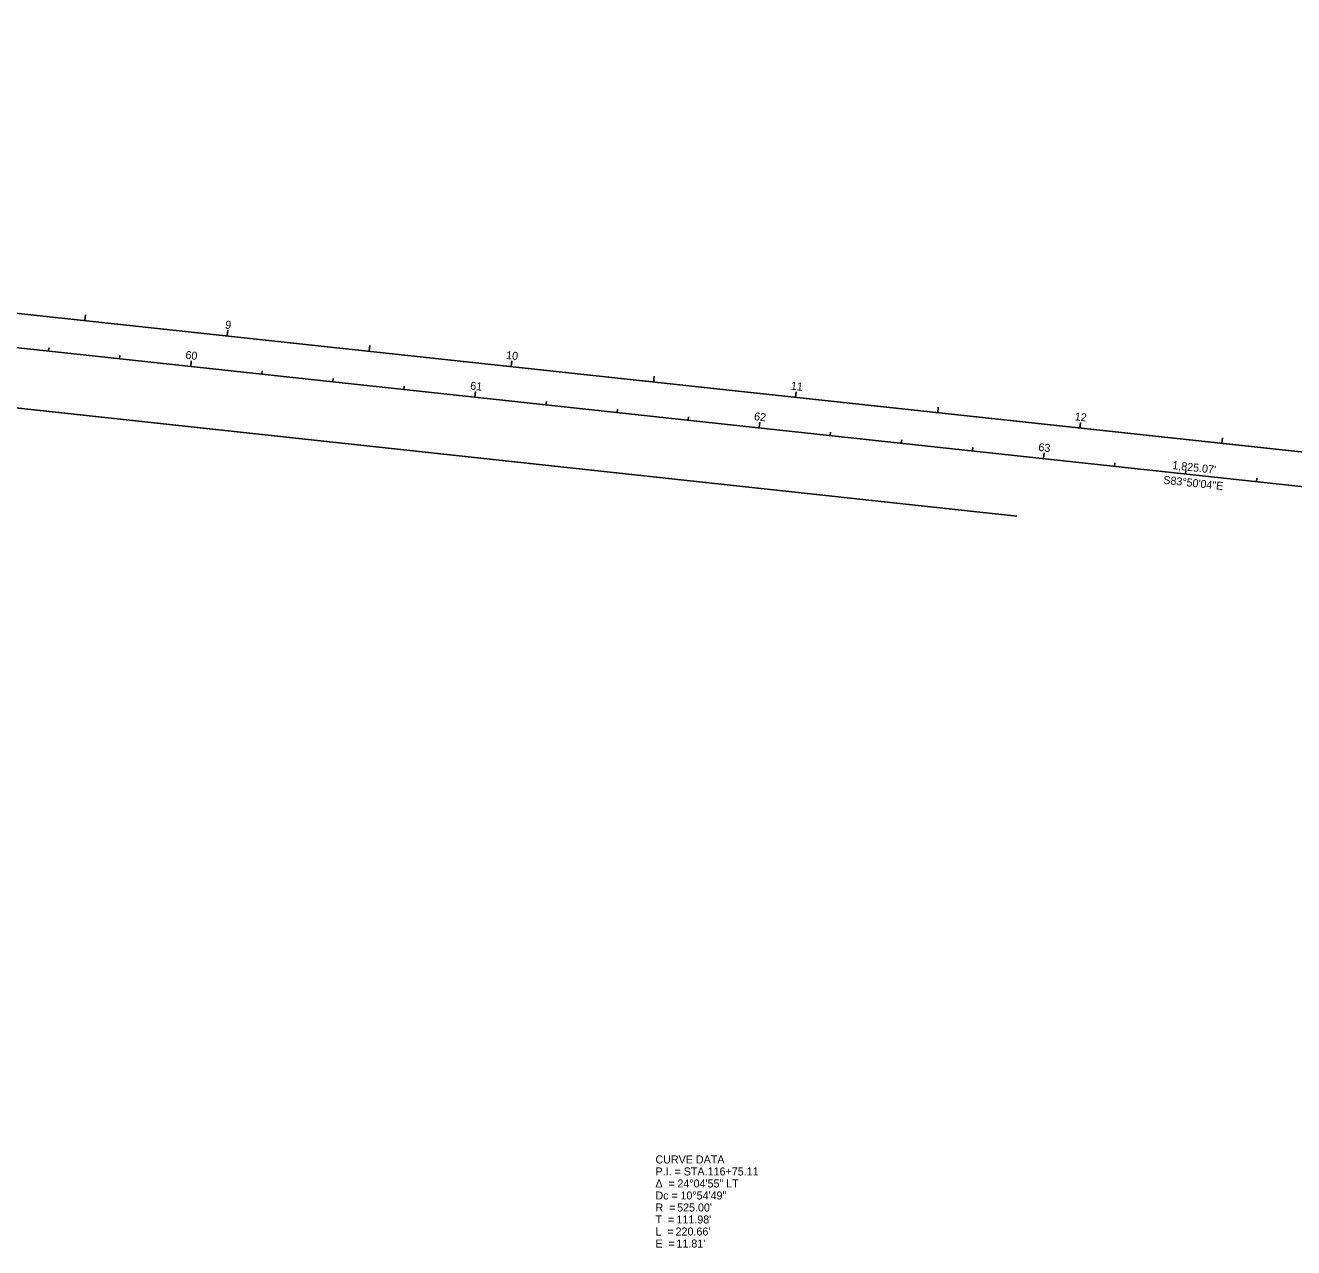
# Model space of a CAD drawing. Extents: x 1363416 to 1365241, y 422393 to 423801.
# Drawn here: x 1364353.9 to 1364797.5, y 422787.9 to 423215.5 of the extents above; entities that cross this region are included whole.
import ezdxf

# ---------------------------------------------------------------- set-up
doc = ezdxf.new("R2010")
doc.units = 0
for name, color, linetype in [('_CIVIL_CONSTRUCTION', 7, 'Continuous'), ('DT_X_Break_Line', 7, 'Continuous'), ('DT_X_Contour_Major', 7, 'Continuous'), ('DT_X_Contour_Minor', 7, 'Continuous'), ('DT_X_Spot_Elev', 7, 'Continuous'), ('MD_P_SAWCUT', 7, 'Continuous'), ('PF_X_Ground_Line', 7, 'Continuous')]:
    doc.layers.add(name, color=color, linetype=linetype)

msp = doc.modelspace()

# ---------------------------------------------------------------- linework, layer by layer
at = {"layer": '_CIVIL_CONSTRUCTION'}
msp.add_line((1363417.51, 423203.55), (1365232.02, 423007.54), dxfattribs=at)
at = {"layer": 'DT_X_Break_Line'}
for p, q in [((1363418.8, 423215.48), (1365233.31, 423019.47)), ((1363773.17, 423144.01), (1364700.72, 423043.81)), ((1363773.17, 423144.01), (1364700.72, 423043.81)), ((1363773.17, 423144.01), (1364700.72, 423043.81)), ((1364295.51, 423120.77), (1365233.31, 423019.47)), ((1365233.31, 423019.47), (1364295.51, 423120.77)), ((1364374.74, 423112.21), (1364374.96, 423114.2)), ((1364424.46, 423106.84), (1364424.67, 423108.83)), ((1364474.17, 423101.47), (1364474.38, 423103.46)), ((1364523.88, 423096.1), (1364524.09, 423098.09)), ((1364573.59, 423090.73), (1364573.8, 423092.72)), ((1364291.61, 423088), (1364700.72, 423043.81)), ((1364291.61, 423088), (1364700.72, 423043.81)), ((1364623.3, 423085.36), (1364623.51, 423087.35)), ((1364673.01, 423079.99), (1364673.22, 423081.98)), ((1364722.72, 423074.62), (1364722.94, 423076.61)), ((1364772.43, 423069.25), (1364772.65, 423071.24))]:
    msp.add_line(p, q, dxfattribs=at)
at = {"layer": 'DT_X_Contour_Major'}
for p, q in [((1364362.01, 423101.52), (1364362.14, 423102.71)), ((1364386.87, 423098.83), (1364387, 423100.03)), ((1364411.72, 423096.15), (1364411.94, 423098.14)), ((1364436.58, 423093.46), (1364436.71, 423094.66)), ((1364461.44, 423090.78), (1364461.56, 423091.97)), ((1364486.29, 423088.09), (1364486.42, 423089.29)), ((1364511.15, 423085.41), (1364511.36, 423087.4)), ((1364536, 423082.72), (1364536.13, 423083.92)), ((1364560.86, 423080.04), (1364560.99, 423081.23)), ((1364585.71, 423077.35), (1364585.84, 423078.55)), ((1364610.57, 423074.67), (1364610.78, 423076.66)), ((1364635.42, 423071.98), (1364635.55, 423073.18)), ((1364660.28, 423069.3), (1364660.41, 423070.49)), ((1364685.13, 423066.61), (1364685.26, 423067.81)), ((1364709.99, 423063.93), (1364710.2, 423065.92)), ((1364734.84, 423061.24), (1364734.97, 423062.44)), ((1364759.7, 423058.56), (1364759.83, 423059.75)), ((1364784.56, 423055.87), (1364784.68, 423057.07))]:
    msp.add_line(p, q, dxfattribs=at)
at = {"layer": 'MD_P_SAWCUT'}
for p, q in [((1364411.72, 423096.15), (1364411.94, 423098.14)), ((1364511.15, 423085.41), (1364511.27, 423086.6)), ((1364610.57, 423074.67), (1364610.7, 423075.86)), ((1364709.99, 423063.93), (1364710.12, 423065.12))]:
    msp.add_line(p, q, dxfattribs=at)

# ---------------------------------------------------------------- texts
at = {"layer": 'DT_X_Break_Line'}
for s, p in [('9', (1364423.65, 423109.44)), ('10', (1364521.93, 423098.83)), ('11', (1364621.55, 423088.07)), ('12', (1364720.84, 423077.34))]:
    msp.add_text(s, height=2.8, rotation=353.8345, dxfattribs=at).set_placement(p)
at = {"layer": 'DT_X_Contour_Major'}
for s, p in [('60', (1364409.78, 423098.87)), ('61', (1364509.39, 423088.11)), ('62', (1364608.69, 423077.39)), ('63', (1364708.12, 423066.64))]:
    msp.add_text(s, height=2.8, rotation=353.8345, dxfattribs=at).set_placement(p)
at = {"layer": 'DT_X_Contour_Minor'}
msp.add_text("1,825.07'", height=2.8, rotation=353.8345, dxfattribs=at).set_placement((1364754.98, 423060.28))
at = {"layer": 'DT_X_Spot_Elev'}
for s, p in [('CURVE DATA', (1364574.3, 422817.39)), ('P.I. = STA. ', (1364574.3, 422813.19)), ('116+75.11', (1364592.56, 422813.19)), ('Δ  = ', (1364574.3, 422808.99)), ('24°04\'55" LT', (1364581.97, 422808.99)), ('Dc = ', (1364574.3, 422804.79)), ('10°54\'49"', (1364583.04, 422804.79)), ('R  = ', (1364574.3, 422800.59)), ("525.00'", (1364581.88, 422800.59)), ('T  = ', (1364574.3, 422796.39)), ("111.98'", (1364581.64, 422796.39)), ('L  = ', (1364574.3, 422792.19)), ("220.66'", (1364581.34, 422792.19)), ('E  = ', (1364574.3, 422787.99)), ("11.81'", (1364581.64, 422787.99))]:
    msp.add_text(s, height=2.8, dxfattribs=at).set_placement(p)
at = {"layer": 'MD_P_SAWCUT'}
msp.add_text('60', height=2.8, rotation=353.8345, dxfattribs=at).set_placement((1364409.78, 423098.87))
at = {"layer": 'PF_X_Ground_Line'}
msp.add_text('S83°50\'04"E', height=2.8, rotation=353.8345, dxfattribs=at).set_placement((1364751.82, 423055.17))

doc.saveas('drawing.dxf')
